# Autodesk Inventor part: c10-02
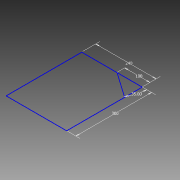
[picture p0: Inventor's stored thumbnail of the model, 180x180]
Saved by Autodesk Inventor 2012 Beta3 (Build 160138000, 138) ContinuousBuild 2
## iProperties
Created: 2011-01
Part Number: c10-02
Material: Aluminum-6061
Document SubType Name: Sheet Metal
Designer: Beta-8540w
Density: 2.71 g/cm^3
Sheet Metal Rule: Aluminum 3 mm
Author: Beta-8540w
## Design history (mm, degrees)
sketch "Sketch1"
  geometry: L1 (0, 0)-(240, 0); L2 (240, 0)-(240, 300); L3 (240, 300)-(0, 300); L4 (0, 300)-(0, 0); L5 (140, 300)-(240, 229.979)
  constraints: 10 end point, 2 parallel, 2 point on line, 1 horizontal, 1 perpendicular
  dimensions: "d0" = 240 distance of L3.end L2.end; "d1" = 300 distance of L2.end L1.end; "d2" = 35 deg angle of L3 L5; "d3" = 100 distance from line of L2 L5.start
other parameters: "Thickness" = 3 (derived), "BendRadius" = 2 (derived), "BendReliefWidth" = 3 (= Thickness), "BendReliefDepth" = 1.5 (= 0.5 x Thickness), "CornerReliefSize" = 12 (= 4 x Thickness), "SeamGap" = 0.01, "MinimumRemnant" = 6 (= 2 x Thickness), "TransitionRadius" = 2 (= BendRadius), "JacobiRadiusSize" = 2 (= BendRadius), "GapSize" = 1.5 (= 0.5 x Thickness)
